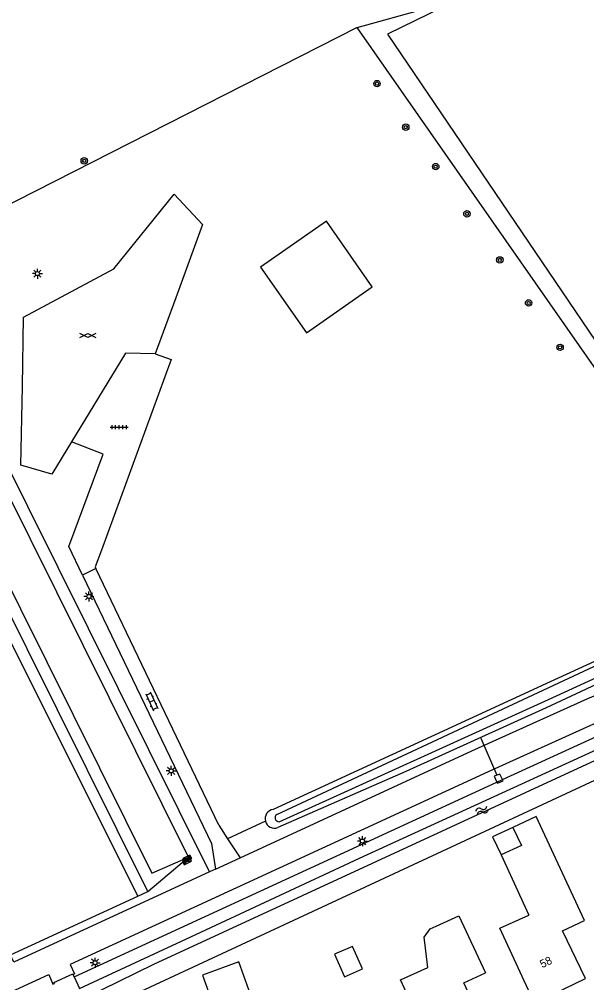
# Model space of a CAD drawing. Extents: x 136000 to 141014, y 402000 to 403500.
# Drawn here: x 137424.5 to 137495.4, y 402412.9 to 402533.2 of the extents above; entities that cross this region are included whole.
import ezdxf

# ---------------------------------------------------------------- set-up
doc = ezdxf.new("R2010")
doc.units = 0
for name, color, linetype in [('gg-afsc-draadraster', 7, 'Continuous'), ('gg-afsc-erfafscheiding', 7, 'Continuous'), ('gg-anno-huisnummerreeks BGT', 7, 'Continuous'), ('gg-bbg-bijgebouw', 7, 'Continuous'), ('gg-bbg-gedigitaliseerde bebouwing', 7, 'Continuous'), ('gg-bbg-gedigitaliseerde bijgebouw', 7, 'Continuous'), ('gg-bbg-hoofdgebouw', 7, 'Continuous'), ('gg-bbg-luifel en loopbrug', 7, 'Continuous'), ('gg-knt-bronhoudergrens', 7, 'Continuous'), ('gg-knt-onverhard', 7, 'Continuous'), ('gg-knt-verharding', 7, 'Continuous'), ('gg-kntw-bovenkant insteek waterloop', 7, 'Continuous'), ('gg-kntw-waterlijn', 7, 'Continuous'), ('gg-kwrk-duiker nz buis', 7, 'Continuous'), ('gg-kwrk-kunstwerk niveau 01', 7, 'Continuous'), ('gg-kwrk-uitstroombak niveau min 01', 7, 'Continuous'), ('gt-grn-groengrens', 7, 'Continuous'), ('gt-grn-groenlijn', 7, 'Continuous'), ('gt-grn-weggrens', 7, 'Continuous'), ('gt-symb-boom', 7, 'Continuous'), ('gt-symb-elektrakast', 7, 'Continuous'), ('gt-symb-gesloten verharding', 7, 'Continuous'), ('gt-symb-klinker verharding', 7, 'Continuous'), ('gt-symb-lichtmast', 7, 'Continuous'), ('gt-symb-tegel verharding', 7, 'Continuous'), ('gt-symb-watersymbool', 7, 'Continuous')]:
    doc.layers.add(name, color=color, linetype=linetype)

# ---------------------------------------------------------------- blocks, each defined once
blk = doc.blocks.new('gt0-BOOM')
at = {"layer": 'gt-symb-boom'}
for radius in [0.4, 0.2]:
    blk.add_circle((0, 0), radius, dxfattribs=at)
blk = doc.blocks.new('gt0-LMAST')
at = {"layer": 'gt-symb-lichtmast'}
for p, q in [((-0.18, 0.17), (-0.45, 0.44)), ((0, 0.25), (0, 0.62)), ((0.17, 0.17), (0.44, 0.44)), ((-0.25, 0), (-0.63, 0)), ((-0.18, -0.18), (-0.45, -0.45)), ((0, -0.25), (0, -0.63)), ((0.44, -0.45), (0.17, -0.18)), ((0.25, 0), (0.62, 0))]:
    blk.add_line(p, q, dxfattribs=at)
blk.add_circle((0, 0), 0.25, dxfattribs=at)
blk = doc.blocks.new('gt0-WA')
at = {"layer": 'gt-symb-watersymbool'}
for centre, start, end in [((-0.32, 0.02), 28.0725, 151.9275), ((0.43, 0.42), 208.0725, 331.9275), ((-0.32, -0.43), 28.0725, 151.9275), ((0.43, -0.03), 208.0725, 331.9275)]:
    blk.add_arc(centre, 0.425, start, end, dxfattribs=at)
blk = doc.blocks.new('gt0-EKAST')
at = {"layer": 'gt-symb-elektrakast'}
for p, q in [((-0.5, -0.25), (0.5, 0.25)), ((-0.5, 0.25), (0.5, -0.25))]:
    blk.add_line(p, q, dxfattribs=at)
blk.add_lwpolyline([(0.5, 0.25), (-0.5, 0.25), (-0.5, -0.25), (0.5, -0.25)], close=True, dxfattribs=at)
blk = doc.blocks.new('gt0-GESVH1')
at = {"layer": 'gt-symb-gesloten verharding'}
for p, q in [((-0.99, -0.26), (0.01, 0.24)), ((0.01, -0.26), (-0.99, 0.24)), ((0.01, 0.24), (1.01, -0.26)), ((1.01, 0.24), (0.01, -0.26))]:
    blk.add_line(p, q, dxfattribs=at)
blk = doc.blocks.new('gt0-TEG1')
at = {"layer": 'gt-symb-tegel verharding'}
for p, q in [((-1.12, 0), (1.12, 0)), ((-0.9, -0.25), (-0.9, 0.25)), ((-0.45, -0.25), (-0.45, 0.25)), ((0, -0.25), (0, 0.25)), ((0.45, -0.25), (0.45, 0.25)), ((0.9, -0.25), (0.9, 0.25))]:
    blk.add_line(p, q, dxfattribs=at)
blk = doc.blocks.new('gt0-KL1')
at = {"layer": 'gt-symb-klinker verharding'}
for p, q in [((-1.15, 0.3), (1.15, 0.3)), ((-1, -0.3), (-1, 0.3)), ((-0.5, 0.3), (-0.5, 0.45)), ((0, -0.3), (0, 0.3)), ((0.5, 0.3), (0.5, 0.45)), ((1, -0.3), (1, 0.3)), ((-1.15, -0.3), (1.15, -0.3)), ((-0.5, -0.45), (-0.5, -0.3)), ((0.5, -0.45), (0.5, -0.3))]:
    blk.add_line(p, q, dxfattribs=at)

msp = doc.modelspace()

# ---------------------------------------------------------------- linework, layer by layer
at = {"layer": 'gg-afsc-draadraster'}
msp.add_lwpolyline([(137549.8, 402475.71), (137528.61, 402505.55), (137516.4, 402523.39), (137501.91, 402544.29), (137496.39, 402544.05), (137470.5, 402531.36), (137518.27, 402460.93)], dxfattribs=at)
at = {"layer": 'gg-afsc-erfafscheiding'}
for p, q in [((137439.32, 402423.7), (137440.6, 402424.29)), ((137405.46, 402408.11), (137439.32, 402423.7))]:
    msp.add_line(p, q, dxfattribs=at)
at = {"layer": 'gg-bbg-bijgebouw'}
msp.add_lwpolyline([(137451.97, 402415.48), (137447.4, 402413.85), (137449.49, 402408.04), (137454.05, 402409.68), (137451.97, 402415.48)], dxfattribs=at)
at = {"layer": 'gg-bbg-gedigitaliseerde bebouwing'}
msp.add_line((137484.7, 402428.85), (137488.17, 402421.34), dxfattribs=at)
for points in [[(137495.11, 402420.64), (137489.09, 402433.64), (137486.19, 402432.29)], [(137486.19, 402432.29), (137487.24, 402430.02), (137484.7, 402428.85)], [(137476.61, 402419.96), (137479.44, 402421.26), (137482.75, 402414.14)], [(137488.88, 402410.35), (137484.54, 402419.7), (137488.17, 402421.34)], [(137475.57, 402414.8), (137475.1, 402418.59), (137475.86, 402419.62), (137476.61, 402419.96)], [(137476.45, 402403.93), (137472.14, 402413.23), (137475.57, 402414.8)]]:
    msp.add_lwpolyline(points, dxfattribs=at)
at = {"layer": 'gg-bbg-gedigitaliseerde bijgebouw'}
msp.add_lwpolyline([(137467.38, 402414.61), (137466.15, 402417.42), (137463.91, 402416.44), (137465.14, 402413.63), (137467.38, 402414.61)], dxfattribs=at)
at = {"layer": 'gg-bbg-hoofdgebouw'}
for points in [[(137488.88, 402410.35), (137495.25, 402413.4), (137492.39, 402419.36), (137495.11, 402420.64)], [(137476.45, 402403.93), (137482.84, 402406.91), (137480.05, 402412.87), (137482.75, 402414.14)]]:
    msp.add_lwpolyline(points, dxfattribs=at)
at = {"layer": 'gg-bbg-luifel en loopbrug'}
msp.add_lwpolyline([(137486.19, 402432.29), (137483.65, 402431.11), (137484.7, 402428.85)], dxfattribs=at)
at = {"layer": 'gg-knt-bronhoudergrens'}
msp.add_lwpolyline([(137378.05, 402463.29), (137380.4, 402479.88), (137383.05, 402484.64), (137404.48, 402493.24), (137439.32, 402423.7)], dxfattribs=at)
at = {"layer": 'gg-knt-onverhard'}
msp.add_lwpolyline([(137460.42, 402494.08), (137468.59, 402499.83), (137462.89, 402508.01), (137454.66, 402502.26), (137460.42, 402494.08)], dxfattribs=at)
at = {"layer": 'gg-knt-verharding'}
for p, q in [((137434.08, 402464.61), (137432.43, 402463.79)), ((137449.44, 402432.57), (137434.08, 402464.61)), ((137432.43, 402463.79), (137448.52, 402430.27)), ((137449.44, 402432.57), (137450.54, 402430.88)), ((137448.52, 402430.27), (137449.04, 402427.07)), ((137450.54, 402430.88), (137452.11, 402428.48)), ((137449.04, 402427.07), (137448.28, 402426.72))]:
    msp.add_line(p, q, dxfattribs=at)
for points in [[(137431.06, 402480.44), (137428.61, 402476.42), (137424.71, 402477.53), (137424.94, 402487.37), (137425.05, 402496.02), (137436.35, 402502.07), (137443.86, 402511.38), (137447.43, 402507.6), (137444.1, 402498.44), (137441.51, 402491.45)], [(137441.51, 402491.45), (137437.81, 402491.51), (137431.06, 402480.44)], [(137441.51, 402491.45), (137443.49, 402490.72), (137434.78, 402466.93), (137433.99, 402464.84), (137434.08, 402464.61)], [(137432.43, 402463.79), (137430.71, 402467.36), (137435.02, 402478.93), (137431.06, 402480.44)], [(137532.74, 402461.43), (137509.95, 402450.99), (137498.89, 402446.39), (137483.09, 402439.21), (137430.89, 402415.16), (137431.43, 402413.99), (137431.26, 402413.92)], [(137452.11, 402428.48), (137481.07, 402441.85), (137495.53, 402448.41), (137505.67, 402452.62)], [(137448.28, 402426.72), (137423.85, 402415.44), (137423.5, 402416.17), (137421.88, 402415.41), (137422.22, 402414.68), (137411.27, 402409.63), (137406.3, 402406.89), (137400.52, 402403.83), (137389.83, 402398.81), (137389.37, 402399.73)], [(137245.82, 402320.72), (137274.92, 402335.54), (137319.32, 402358.61), (137333.43, 402366.09), (137346.73, 402373.33), (137362.01, 402381.23), (137375.19, 402387.74), (137387.81, 402394.29), (137403.54, 402401.78), (137408.29, 402404.33), (137412.62, 402406.74), (137428.23, 402413.9), (137428.73, 402412.72), (137428.91, 402412.8)]]:
    msp.add_lwpolyline(points, dxfattribs=at)
at = {"layer": 'gg-kntw-bovenkant insteek waterloop'}
for p, q in [((137484.87, 402438.26), (137522.93, 402455.78)), ((137501.29, 402440.44), (137434.13, 402409.22)), ((137431.38, 402413.64), (137484.18, 402437.95)), ((137484.18, 402437.95), (137484.87, 402438.26))]:
    msp.add_line(p, q, dxfattribs=at)
for points in [[(137543.87, 402470.51), (137531.07, 402464.77), (137517.11, 402458.48), (137514.85, 402458.71), (137513.76, 402458.15), (137509.85, 402456.36), (137490.32, 402447.23), (137472.79, 402439.26), (137456.82, 402432.26)], [(137513, 402460.86), (137505.45, 402457.19), (137490.84, 402450.48), (137456.23, 402434.52)]]:
    msp.add_lwpolyline(points, dxfattribs=at)
for start, end in [(98.6831, 194.7175), (194.6455, 290.6728)]:
    msp.add_arc((137456.41, 402433.36), 1.18, start, end, dxfattribs=at)
at = {"layer": 'gg-kntw-waterlijn'}
msp.add_line((137456.69, 402433.92), (137514.31, 402460.82), dxfattribs=at)
for points in [[(137456.99, 402433), (137490.61, 402448.27), (137515.32, 402459.58), (137518.46, 402459.52), (137542.3, 402470.76)], [(137432.06, 402412.15), (137445.95, 402418.61), (137467.03, 402428.44), (137505.11, 402445.9), (137532.42, 402458.66), (137532.88, 402457.68), (137496.99, 402440.91), (137441.28, 402415.18), (137432.63, 402410.9)]]:
    msp.add_lwpolyline(points, dxfattribs=at)
msp.add_arc((137456.98, 402433.51), 0.507, 125.7928, 271.1519, dxfattribs=at)
at = {"layer": 'gg-kwrk-duiker nz buis'}
msp.add_line((137484.2, 402438.76), (137482.21, 402443.4), dxfattribs=at)
at = {"layer": 'gg-kwrk-kunstwerk niveau 01'}
for p, q in [((137428.86, 402412.91), (137431.23, 402413.98)), ((137431.23, 402413.98), (137431.26, 402413.92)), ((137431.38, 402413.64), (137431.26, 402413.92)), ((137431.38, 402413.64), (137432.06, 402412.15)), ((137428.86, 402412.91), (137428.91, 402412.8))]:
    msp.add_line(p, q, dxfattribs=at)
at = {"layer": 'gg-kwrk-uitstroombak niveau min 01'}
for points in [[(137484.87, 402438.26), (137484.54, 402438.95), (137483.86, 402438.67), (137484.18, 402437.95)], [(137484.18, 402437.95), (137484.25, 402437.8), (137484.95, 402438.1), (137484.87, 402438.26)]]:
    msp.add_lwpolyline(points, dxfattribs=at)
at = {"layer": 'gt-grn-groengrens'}
for p, q in [((137466.71, 402532.22), (137474.09, 402534.25)), ((137466.71, 402532.22), (137410.13, 402503.43)), ((137516.9, 402460.29), (137466.71, 402532.22)), ((137448.28, 402426.72), (137410.13, 402503.43)), ((137455.27, 402433.06), (137450.54, 402430.88)), ((137440.6, 402424.29), (137440.49, 402424.43))]:
    msp.add_line(p, q, dxfattribs=at)
for points in [[(137440.49, 402424.43), (137403, 402499.8), (137410.13, 402503.43)], [(137445.68, 402428.58), (137409.46, 402501.41), (137405, 402499.14), (137441.09, 402426.58), (137445.68, 402428.58)]]:
    msp.add_lwpolyline(points, dxfattribs=at)
at = {"layer": 'gt-grn-groenlijn'}
msp.add_line((137440.6, 402424.29), (137445.68, 402428.58), dxfattribs=at)
at = {"layer": 'gt-grn-weggrens'}
msp.add_line((137449.04, 402427.07), (137452.11, 402428.48), dxfattribs=at)

# ---------------------------------------------------------------- block references
at = {"layer": 'gt-symb-boom'}
for p in [(137469.21, 402525.2), (137472.8, 402519.76), (137432.64, 402515.55), (137476.54, 402514.83), (137480.44, 402508.93), (137484.55, 402503.18), (137488.14, 402497.8), (137492.07, 402492.26)]:
    msp.add_blockref('gt0-BOOM', p, dxfattribs=at)
at = {"layer": 'gt-symb-elektrakast'}
for p, rotation in [((137445.46, 402428.06), 26.915115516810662), ((137445.51, 402428.39), 26.915115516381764)]:
    msp.add_blockref('gt0-EKAST', p, dxfattribs=dict(at, rotation=rotation))
at = {"layer": 'gt-symb-gesloten verharding'}
msp.add_blockref('gt0-GESVH1', (137433.09, 402493.73), dxfattribs=at)
at = {"layer": 'gt-symb-klinker verharding', "rotation": -65.22886109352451}
msp.add_blockref('gt0-KL1', (137441.08, 402448.04), dxfattribs=at)
at = {"layer": 'gt-symb-lichtmast'}
for p in [(137426.79, 402501.46), (137433.23, 402461.15), (137443.5, 402439.35), (137467.38, 402430.58), (137434, 402415.39)]:
    msp.add_blockref('gt0-LMAST', p, dxfattribs=at)
at = {"layer": 'gt-symb-tegel verharding'}
msp.add_blockref('gt0-TEG1', (137437.01, 402482.27), dxfattribs=at)
at = {"layer": 'gt-symb-watersymbool', "rotation": 24.643095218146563}
msp.add_blockref('gt0-WA', (137482.27, 402434.39), dxfattribs=at)

# ---------------------------------------------------------------- texts
at = {"layer": 'gg-anno-huisnummerreeks BGT'}
msp.add_text('58', height=1, rotation=25.6, dxfattribs=at).set_placement((137489.84, 402414.69))

doc.saveas('drawing.dxf')
